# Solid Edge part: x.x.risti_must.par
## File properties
Author: Romil
Template: iso part.par
Last saved by: Romil
Revision: 38
Application: Solid Edge
Accuracy: 0.990
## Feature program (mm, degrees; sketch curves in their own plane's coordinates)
sketch for "unnamed Protrusion 1" plane through (0, 0, 0) normal (1, 0, 0) x-axis (0, 1, 0)
extrude "unnamed Protrusion 1" add finite 7.8 symmetric
sketch for "unnamed RevolvedCutout 1" plane through (0, 0, 0) normal (0, -1, 0) x-axis (1, 0, 0)
revolve "unnamed RevolvedCutout 1" cut finite 360 deg
sketch for "ExtrudedProtrusion_11" plane through (0, 0, 11.6) normal (0, 0, 1) x-axis (1, 0, 0)
extrude "ExtrudedProtrusion_11" add finite 6.8 along -normal
sketch for "unnamed Protrusion 2" plane through (0, 0, 11.6) normal (0, 0, 1) x-axis (1, 0, 0)
extrude "unnamed Protrusion 2" add finite 1.2 along -normal
sketch for "unnamed Protrusion 3" plane through (0, 0, 0) normal (0, 0, 1) x-axis (1, 0, 0)
extrude "unnamed Protrusion 3" add to key point along +normal
sketch for "unnamed Protrusion 4" plane through (0, 0, 0) normal (0, 0, 1) x-axis (1, 0, 0)
extrude "unnamed Protrusion 4" add to key point along +normal
mirror "unnamed Mirror 1" of "unnamed Protrusion 3" about plane through (0, 0, 0) normal (1, 0, 0)
extrude "unnamed Protrusion 5" add finite 4.8
sketch used by "unnamed Protrusion 6" plane through (0, 0, 0) normal (0, -1, 0) x-axis (1, 0, 0)
extrude "unnamed Protrusion 6" add to key point symmetric
sketch for "unnamed Cutout 1" plane through (0, 0, 11.6) normal (0, 0, 1) x-axis (1, 0, 0)
extrude "unnamed Cutout 1" cut to key point symmetric
sketch for "unnamed Cutout 2" plane through (0, 0, 0) normal (1, 0, 0) x-axis (0, 1, 0)
extrude "unnamed Cutout 2" cut finite 47.4999 symmetric
sketch for "ExtrudedCutout_25" plane through (0, 0, 0) normal (0, -1, 0) x-axis (1, 0, 0)
  circle centre (0, 0) radius 3.6
extrude "ExtrudedCutout_25" cut finite 152.9831 symmetric
sketch used by "ExtrudedCutout_26" plane through (0, 0, 0) normal (0, -1, 0) x-axis (1, 0, 0)
  line (0.6, 9.8798) -> (0.6, 5.3861)
  line (-0.6, 5.3861) -> (-0.6, 9.8798)
  line (0.6, 5.3861) -> (0.6, 4.8)
  line (0.6, 4.8) -> (-0.6, 4.8)
  line (-0.6, 4.8) -> (-0.6, 5.3861)
  line (-0.6, 9.8798) -> (-0.6, 10.4)
  line (-0.6, 10.4) -> (0.6, 10.4)
  line (0.6, 10.4) -> (0.6, 9.8798)
extrude "ExtrudedCutout_26" cut finite 35.3769 symmetric
fillet "unnamed Round 1"
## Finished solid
Body 1: solid body, 120 faces, 320 edges, 200 vertices.
  Faces by surface: cylinder 63, plane 43, blend 12, torus 2
  Edges by curve: line 170, circle 94, intersection 32, ellipse 24
Bounding box of the edges (mm; curved faces can reach further): 7.800 x 7.200 x 15.200, from (-3.9, -3.6, -3.6) to (3.9, 3.6, 11.6).
Cylindrical faces by radius (mm): R0.1 x8, R0.2 x8, R0.4 x24, R2.2319 x4, R2.35 x8, R2.7009 x2, R3.0587 x3, R3.6 x6
Toroidal faces (ring radius, tube radius in mm): R3.3 r0.3 x2
Planar faces by outward normal: +x 9, +y 6, +z 6, -x 9, -y 6, -z 7
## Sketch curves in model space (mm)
arc centre (0.975, -0.975, 11.6) radius 0.1 from (0.875, -0.975, 11.6) through (0.9064, -0.9023, 11.6) to (0.975, -0.875, 11.6)
line (0.975, -0.875, 11.6) -> (2.181, -0.875, 11.6)
arc centre (0, 0, 11.6) radius 2.35 from (2.181, 0.875, 11.6) through (2.35, 0, 11.6) to (2.181, -0.875, 11.6)
line (2.181, 0.875, 11.6) -> (0.975, 0.875, 11.6)
arc centre (0.975, 0.975, 11.6) radius 0.1 from (0.975, 0.875, 11.6) through (0.9023, 0.9064, 11.6) to (0.875, 0.975, 11.6)
line (0.875, 0.975, 11.6) -> (0.875, 2.181, 11.6)
arc centre (0, 0, 11.6) radius 2.35 from (-0.875, 2.181, 11.6) through (0, 2.35, 11.6) to (0.875, 2.181, 11.6)
line (-0.875, 2.181, 11.6) -> (-0.875, 0.975, 11.6)
arc centre (-0.975, 0.975, 11.6) radius 0.1 from (-0.875, 0.975, 11.6) through (-0.9064, 0.9023, 11.6) to (-0.975, 0.875, 11.6)
line (-0.975, 0.875, 11.6) -> (-2.181, 0.875, 11.6)
arc centre (0, 0, 11.6) radius 2.35 from (-2.181, -0.875, 11.6) through (-2.35, 0, 11.6) to (-2.181, 0.875, 11.6)
line (-2.181, -0.875, 11.6) -> (-0.975, -0.875, 11.6)
arc centre (-0.975, -0.975, 11.6) radius 0.1 from (-0.975, -0.875, 11.6) through (-0.9023, -0.9064, 11.6) to (-0.875, -0.975, 11.6)
line (-0.875, -0.975, 11.6) -> (-0.875, -2.181, 11.6)
arc centre (0, 0, 11.6) radius 2.35 from (0.875, -2.181, 11.6) through (0, -2.35, 11.6) to (-0.875, -2.181, 11.6)
line (0.875, -2.181, 11.6) -> (0.875, -0.975, 11.6)
circle centre (0, 0, 11.6) radius 2.7009
arc centre (-0.975, -0.975, 0) radius 0.1 from (-0.975, -0.875, 0) through (-0.9023, -0.9064, 0) to (-0.875, -0.975, 0)
line (-0.875, -0.975, 0) -> (-0.875, -2.181, 0)
arc centre (0, 0, 0) radius 2.35 from (0.875, -2.181, 0) through (0, -2.35, 0) to (-0.875, -2.181, 0)
line (0.875, -2.181, 0) -> (0.875, -0.975, 0)
arc centre (0.975, -0.975, 0) radius 0.1 from (0.875, -0.975, 0) through (0.9064, -0.9023, 0) to (0.975, -0.875, 0)
line (0.975, -0.875, 0) -> (2.181, -0.875, 0)
arc centre (0, 0, 0) radius 2.35 from (2.181, 0.875, 0) through (2.35, 0, 0) to (2.181, -0.875, 0)
line (2.181, 0.875, 0) -> (0.975, 0.875, 0)
arc centre (0.975, 0.975, 0) radius 0.1 from (0.975, 0.875, 0) through (0.9023, 0.9064, 0) to (0.875, 0.975, 0)
line (0.875, 0.975, 0) -> (0.875, 2.181, 0)
arc centre (0, 0, 0) radius 2.35 from (-0.875, 2.181, 0) through (0, 2.35, 0) to (0.875, 2.181, 0)
line (-0.875, 2.181, 0) -> (-0.875, 0.975, 0)
arc centre (-0.975, 0.975, 0) radius 0.1 from (-0.875, 0.975, 0) through (-0.9064, 0.9023, 0) to (-0.975, 0.875, 0)
line (-0.975, 0.875, 0) -> (-2.181, 0.875, 0)
arc centre (0, 0, 0) radius 2.35 from (-2.181, -0.875, 0) through (-2.35, 0, 0) to (-2.181, 0.875, 0)
line (-2.181, -0.875, 0) -> (-0.975, -0.875, 0)
arc centre (1.1947, 3.1832, 0) radius 0.2 from (1.3919, 3.2163, 0) through (1.349, 3.3104, 0) to (1.2649, 3.3705, 0)
arc centre (3.593, 3.586, 0) radius 2.2319 from (3.219, 1.3856, 0) through (1.9675, 2.0565, 0) to (1.3919, 3.2163, 0)
arc centre (3.1855, 1.1884, 0) radius 0.2 from (3.3729, 1.2583, 0) through (3.313, 1.3425, 0) to (3.219, 1.3856, 0)
arc centre (0, 0, 0) radius 3.6 from (3.3729, 1.2583, 0) through (3.6, 0, 0) to (3.3729, -1.2583, 0)
arc centre (3.1855, -1.1884, 0) radius 0.2 from (3.219, -1.3856, 0) through (3.313, -1.3425, 0) to (3.3729, -1.2583, 0)
arc centre (3.593, -3.586, 0) radius 2.2319 from (3.219, -1.3856, 0) through (1.9675, -2.0565, 0) to (1.3919, -3.2163, 0)
arc centre (1.1947, -3.1832, 0) radius 0.2 from (1.2649, -3.3705, 0) through (1.349, -3.3104, 0) to (1.3919, -3.2163, 0)
arc centre (0, 0, 0) radius 3.6 from (1.2649, -3.3705, 0) through (0, -3.6, 0) to (-1.2649, -3.3705, 0)
arc centre (-1.1947, -3.1832, 0) radius 0.2 from (-1.3919, -3.2163, 0) through (-1.349, -3.3104, 0) to (-1.2649, -3.3705, 0)
arc centre (-3.593, -3.586, 0) radius 2.2319 from (-3.219, -1.3856, 0) through (-1.9675, -2.0565, 0) to (-1.3919, -3.2163, 0)
arc centre (-3.1855, -1.1884, 0) radius 0.2 from (-3.3729, -1.2583, 0) through (-3.313, -1.3425, 0) to (-3.219, -1.3856, 0)
arc centre (0, 0, 0) radius 3.6 from (-3.3729, -1.2583, 0) through (-3.6, 0, 0) to (-3.3729, 1.2583, 0)
arc centre (-3.1855, 1.1884, 0) radius 0.2 from (-3.219, 1.3856, 0) through (-3.313, 1.3425, 0) to (-3.3729, 1.2583, 0)
arc centre (-3.593, 3.586, 0) radius 2.2319 from (-3.219, 1.3856, 0) through (-1.9675, 2.0565, 0) to (-1.3919, 3.2163, 0)
arc centre (-1.1947, 3.1832, 0) radius 0.2 from (-1.2649, 3.3705, 0) through (-1.349, 3.3104, 0) to (-1.3919, 3.2163, 0)
arc centre (0, 0, 0) radius 3.6 from (-1.2649, 3.3705, 0) through (0, 3.6, 0) to (1.2649, 3.3705, 0)
line (3.6217, 0, 4.8) -> (3.6217, 0, 3.8)
line (3.6217, 0, 3.8) -> (-3.6217, 0, 3.8)
line (-3.6217, 0, 3.8) -> (-3.6217, 0, 4.8)
line (-3.6217, 0, 4.8) -> (3.6217, 0, 4.8)
line (2.7, 0, -0.6) -> (2.7, 0, 0.6)
line (2.7, 0, 0.6) -> (-2.7, 0, 0.6)
line (-2.7, 0, 0.6) -> (-2.7, 0, -0.6)
line (-2.7, 0, -0.6) -> (2.7, 0, -0.6)
line (-3.35, -0.6, 0) -> (-3.35, 0.6, 0)
line (-3.35, 0.6, 0) -> (3.35, 0.6, 0)
line (3.35, 0.6, 0) -> (3.35, -0.6, 0)
line (3.35, -0.6, 0) -> (-3.35, -0.6, 0)
line (0.6, 0, 5.3861) -> (0.6, 0, 4.8)
line (0.6, 0, 4.8) -> (-0.6, 0, 4.8)
line (-0.6, 0, 4.8) -> (-0.6, 0, 5.3861)
line (-0.6, 0, 5.3861) -> (-0.6, 0, 9.8798)
line (-0.6, 0, 9.8798) -> (-0.6, 0, 10.4)
line (-0.6, 0, 10.4) -> (0.6, 0, 10.4)
line (0.6, 0, 10.4) -> (0.6, 0, 9.8798)
line (0.6, 0, 9.8798) -> (0.6, 0, 5.3861)
line (-4.4651, 0, 0) -> (5.0671, 0, 0)
line (2.7, 0, 3.0587) -> (2.7, 0, 3.3)
arc centre (3, 0, 3.3) radius 0.3 from (2.7, 0, 3.3) through (2.7941, 0, 3.5182) to (3, 0, 3.6)
line (3, 0, 3.6) -> (3.9, 0, 3.6)
line (3.9, 0, 3.6) -> (3.9, 0, 4.041)
line (3.9, 0, 4.041) -> (-3.9, 0, 4.041)
line (-3.9, 0, 4.041) -> (-3.9, 0, 3.6)
line (-3.9, 0, 3.6) -> (-3, 0, 3.6)
arc centre (-3, 0, 3.3) radius 0.3 from (-2.7, 0, 3.3) through (-2.7941, 0, 3.5182) to (-3, 0, 3.6)
line (-2.7, 0, 3.3) -> (-2.7, 0, 3.0587)
line (-2.7, 0, 3.0587) -> (2.7, 0, 3.0587)
circle centre (0, 0, 7.9783) radius 2.4
circle centre (0, 0, 7.9783) radius 3.6217
line (-3.6217, -2.75, 0) -> (-3.6217, 1.953, 0)
line (-3.6217, -2.75, 0) -> (-2.7879, -2.75, 0)
line (-2.7879, 2.75, 0) -> (-2.7879, -2.75, 0)
line (-3.6217, 2.75, 0) -> (-2.7879, 2.75, 0)
line (-3.6217, 2.75, 0) -> (-3.6217, 1.953, 0)
circle centre (0, 0, 0) radius 3.6
arc centre (3.593, -3.586, 11.6) radius 2.2319 from (3.219, -1.3856, 11.6) through (1.9675, -2.0565, 11.6) to (1.3919, -3.2163, 11.6)
arc centre (3.1855, -1.1884, 11.6) radius 0.2 from (3.219, -1.3856, 11.6) through (3.313, -1.3425, 11.6) to (3.3729, -1.2583, 11.6)
arc centre (0, 0, 11.6) radius 3.6 from (3.3729, 1.2583, 11.6) through (3.6, 0, 11.6) to (3.3729, -1.2583, 11.6)
arc centre (3.1855, 1.1884, 11.6) radius 0.2 from (3.3729, 1.2583, 11.6) through (3.313, 1.3425, 11.6) to (3.219, 1.3856, 11.6)
arc centre (3.593, 3.586, 11.6) radius 2.2319 from (3.219, 1.3856, 11.6) through (1.9675, 2.0565, 11.6) to (1.3919, 3.2163, 11.6)
arc centre (1.1947, 3.1832, 11.6) radius 0.2 from (1.3919, 3.2163, 11.6) through (1.349, 3.3104, 11.6) to (1.2649, 3.3705, 11.6)
arc centre (0, 0, 11.6) radius 3.6 from (-1.2649, 3.3705, 11.6) through (0, 3.6, 11.6) to (1.2649, 3.3705, 11.6)
arc centre (-1.1947, 3.1832, 11.6) radius 0.2 from (-1.2649, 3.3705, 11.6) through (-1.349, 3.3104, 11.6) to (-1.3919, 3.2163, 11.6)
arc centre (-3.593, 3.586, 11.6) radius 2.2319 from (-3.219, 1.3856, 11.6) through (-1.9675, 2.0565, 11.6) to (-1.3919, 3.2163, 11.6)
arc centre (-3.1855, 1.1884, 11.6) radius 0.2 from (-3.219, 1.3856, 11.6) through (-3.313, 1.3425, 11.6) to (-3.3729, 1.2583, 11.6)
arc centre (0, 0, 11.6) radius 3.6 from (-3.3729, -1.2583, 11.6) through (-3.6, 0, 11.6) to (-3.3729, 1.2583, 11.6)
arc centre (-3.1855, -1.1884, 11.6) radius 0.2 from (-3.3729, -1.2583, 11.6) through (-3.313, -1.3425, 11.6) to (-3.219, -1.3856, 11.6)
arc centre (-3.593, -3.586, 11.6) radius 2.2319 from (-3.219, -1.3856, 11.6) through (-1.9675, -2.0565, 11.6) to (-1.3919, -3.2163, 11.6)
arc centre (-1.1947, -3.1832, 11.6) radius 0.2 from (-1.3919, -3.2163, 11.6) through (-1.349, -3.3104, 11.6) to (-1.2649, -3.3705, 11.6)
arc centre (0, 0, 11.6) radius 3.6 from (1.2649, -3.3705, 11.6) through (0, -3.6, 11.6) to (-1.2649, -3.3705, 11.6)
arc centre (1.1947, -3.1832, 11.6) radius 0.2 from (1.2649, -3.3705, 11.6) through (1.349, -3.3104, 11.6) to (1.3919, -3.2163, 11.6)
circle centre (0, 0, 8) radius 3.6
arc centre (0, -0.975, -0.975) radius 0.1 from (0, -0.975, -0.875) through (0, -0.9023, -0.9064) to (0, -0.875, -0.975)
line (0, -0.875, -0.975) -> (0, -0.875, -2.181)
arc centre (0, 0, 0) radius 2.35 from (0, 0.875, -2.181) through (0, 0, -2.35) to (0, -0.875, -2.181)
line (0, 0.875, -2.181) -> (0, 0.875, -0.975)
arc centre (0, 0.975, -0.975) radius 0.1 from (0, 0.875, -0.975) through (0, 0.9064, -0.9023) to (0, 0.975, -0.875)
line (0, 0.975, -0.875) -> (0, 2.181, -0.875)
arc centre (0, 0, 0) radius 2.35 from (0, 2.181, 0.875) through (0, 2.35, 0) to (0, 2.181, -0.875)
line (0, 2.181, 0.875) -> (0, 0.975, 0.875)
arc centre (0, 0.975, 0.975) radius 0.1 from (0, 0.975, 0.875) through (0, 0.9023, 0.9064) to (0, 0.875, 0.975)
line (0, 0.875, 0.975) -> (0, 0.875, 2.181)
arc centre (0, 0, 0) radius 2.35 from (0, -0.875, 2.181) through (0, 0, 2.35) to (0, 0.875, 2.181)
line (0, -0.875, 2.181) -> (0, -0.875, 0.975)
arc centre (0, -0.975, 0.975) radius 0.1 from (0, -0.875, 0.975) through (0, -0.9064, 0.9023) to (0, -0.975, 0.875)
line (0, -0.975, 0.875) -> (0, -2.181, 0.875)
arc centre (0, 0, 0) radius 2.35 from (0, -2.181, -0.875) through (0, -2.35, 0) to (0, -2.181, 0.875)
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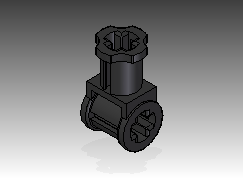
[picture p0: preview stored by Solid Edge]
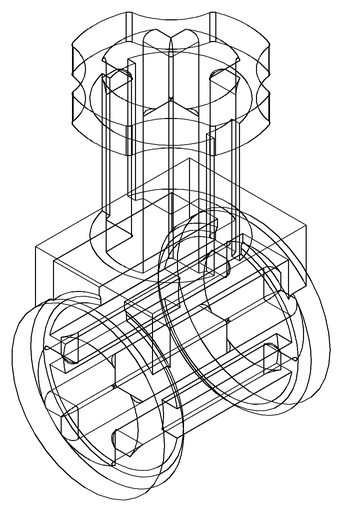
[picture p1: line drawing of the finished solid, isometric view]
